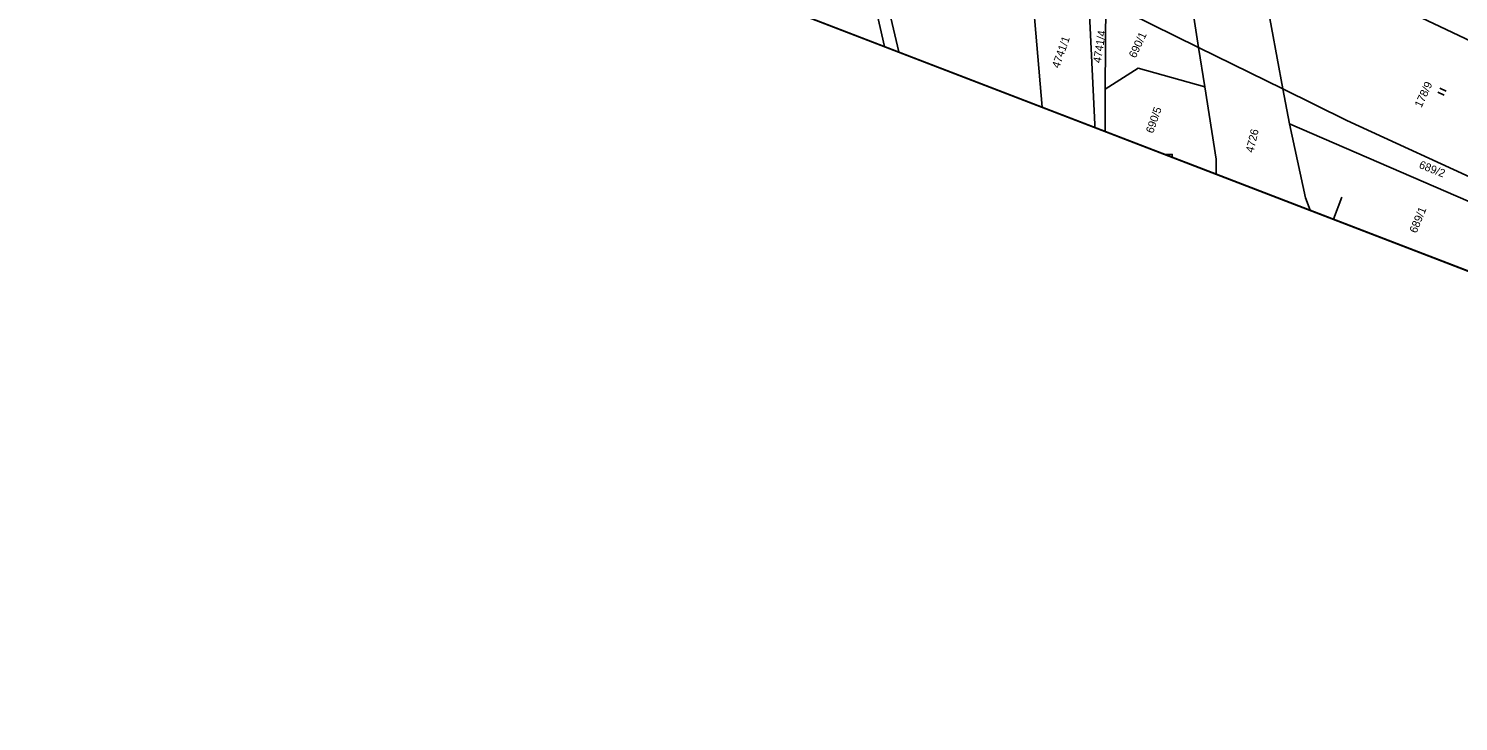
# Model space of a CAD drawing. Extents: x -755344 to -754413, y -1162670 to -1161477.
# Drawn here: x -755344.1 to -755040.4, y -1162670.3 to -1162523.1 of the extents above; entities that cross this region are included whole.
import ezdxf

# ---------------------------------------------------------------- set-up
doc = ezdxf.new("R2010")
doc.units = 0
for name, color, linetype in [('Formát', 7, 'Continuous'), ('Katastrální hranice', 7, 'Continuous'), ('Vrstva 55', 7, 'Continuous'), ('Vrstva 57', 7, 'Continuous'), ('Vrstva 58', 7, 'Continuous')]:
    doc.layers.add(name, color=color, linetype=linetype)

msp = doc.modelspace()

# ---------------------------------------------------------------- linework, layer by layer
at = {"layer": 'Formát'}
for p, q in [((-755344.08, -1162456.97), (-754789.71, -1162670.32)), ((-755066.89, -1162563.65), (-755065.1, -1162558.98))]:
    msp.add_line(p, q, dxfattribs=at)
msp.add_lwpolyline([(-754488.01, -1161886.37), (-754789.71, -1162670.32), (-755344.08, -1162456.97), (-755042.37, -1161673.02)], close=True, dxfattribs=at)
msp.add_lwpolyline([(-755344.08, -1162456.97), (-754789.71, -1162670.32), (-754488.01, -1161886.37), (-755042.37, -1161673.02)], dxfattribs=at)
msp.add_lwpolyline([(-755344.08, -1162456.97), (-754789.71, -1162670.32), (-754488.01, -1161886.37), (-755042.37, -1161673.02)], dxfattribs=at)
at = {"layer": 'Katastrální hranice'}
msp.add_line((-755064.06, -1162542.65), (-755010.16, -1162567.43), dxfattribs=at)
at = {"layer": 'Vrstva 55'}
for p, q in [((-755169.63, -1162495.32), (-755162.24, -1162526.95)), ((-754997.93, -1162544.71), (-755083.94, -1162503.85)), ((-755115.23, -1162517.45), (-755115.39, -1162536.04)), ((-755095.54, -1162527.15), (-755115.23, -1162517.45)), ((-755095.54, -1162527.15), (-755115.23, -1162517.45)), ((-755094.23, -1162535.53), (-755095.54, -1162527.15)), ((-755077.64, -1162535.97), (-755064.06, -1162542.65)), ((-755077.64, -1162535.97), (-755064.06, -1162542.65)), ((-755077.64, -1162535.97), (-755076.22, -1162543.36)), ((-755064.06, -1162542.65), (-755010.16, -1162567.43)), ((-755064.06, -1162542.65), (-755010.16, -1162567.43)), ((-755030.16, -1162563.38), (-755076.22, -1162543.36)), ((-755076.22, -1162543.36), (-755072.83, -1162559.11))]:
    msp.add_line(p, q, dxfattribs=at)
for points in [[(-755128.8, -1162539.82), (-755131.98, -1162502.55), (-755133.78, -1162491.69)], [(-755159.22, -1162528.11), (-755167.04, -1162494.84)], [(-755095.54, -1162527.15), (-755098.96, -1162504.9), (-755101.11, -1162495.7)], [(-755083.94, -1162503.85), (-755082.47, -1162509.84), (-755077.64, -1162535.97)], [(-755117.62, -1162544.13), (-755117.62, -1162543.52), (-755118.95, -1162515.63)], [(-755095.54, -1162527.15), (-755084.75, -1162532.46), (-755077.64, -1162535.97)], [(-755095.54, -1162527.15), (-755084.75, -1162532.46), (-755077.64, -1162535.97)], [(-755115.39, -1162536.04), (-755108.39, -1162531.55), (-755094.23, -1162535.53)], [(-755115.39, -1162536.04), (-755115.42, -1162544.97)], [(-755091.81, -1162554.06), (-755091.84, -1162550.88), (-755094.23, -1162535.53)], [(-755101.14, -1162550.47), (-755101.14, -1162549.87), (-755102.7, -1162549.87)], [(-755072.83, -1162559.11), (-755071.86, -1162561.73)]]:
    msp.add_lwpolyline(points, dxfattribs=at)
at = {"layer": 'Vrstva 58'}
for p, q in [((-755043.41, -1162537.31), (-755044.77, -1162536.68)), ((-755042.98, -1162536.41), (-755044.34, -1162535.77))]:
    msp.add_line(p, q, dxfattribs=at)

# ---------------------------------------------------------------- texts
at = {"layer": 'Vrstva 57'}
for s, rotation, p in [('4741/4', 81, (-755116.32, -1162530.55)), ('690/1', 65, (-755108.94, -1162529.54)), ('4741/1', 70.5734, (-755125.18, -1162531.7)), ('178/9', 65, (-755048.23, -1162540.07)), ('690/5', 70.8343, (-755105.22, -1162545.52)), ('4726', 76.4903, (-755083.94, -1162549.62)), ('689/2', 338.336, (-755048.89, -1162552.71)), ('689/1', 67.7974, (-755049.28, -1162566.73))]:
    msp.add_text(s, height=1.7, rotation=rotation, dxfattribs=at).set_placement(p)

doc.saveas('drawing.dxf')
